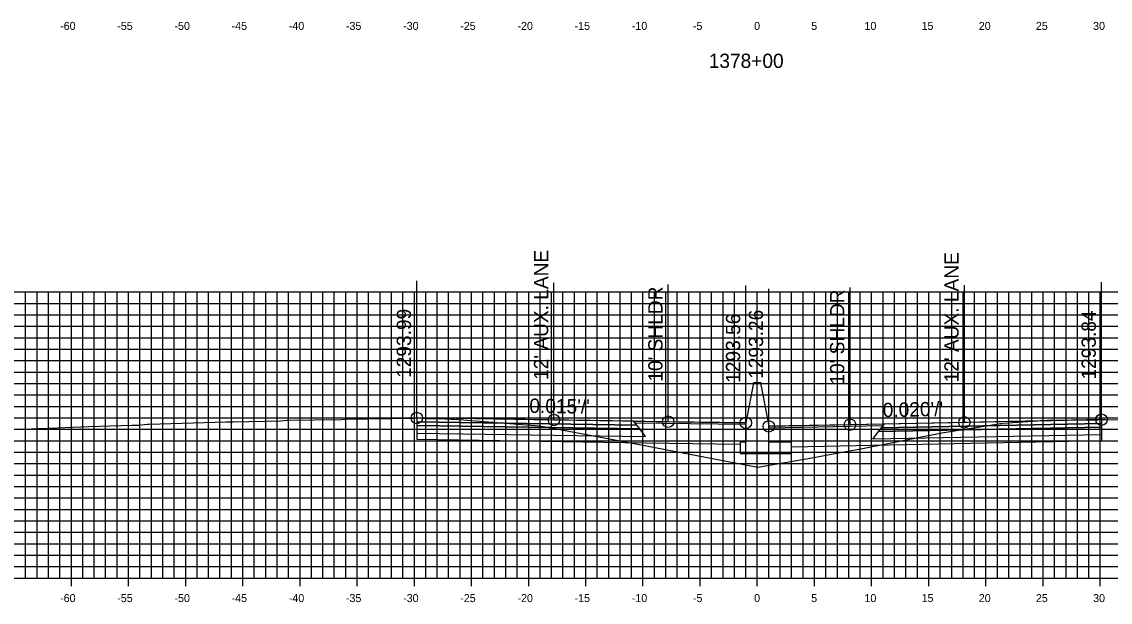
# Model space of a CAD drawing. Extents: x 674939 to 678919, y 750652 to 765176.
# Drawn here: x 678674.2 to 678769.4, y 754945.4 to 754996.2 of the extents above; entities that cross this region are included whole.
import ezdxf

# ---------------------------------------------------------------- set-up
doc = ezdxf.new("R2010")
doc.units = 0
for name, color, linetype in [('Level 10', 7, 'Continuous'), ('Level 17', 7, 'Continuous'), ('Level 18', 7, 'Continuous'), ('Level 19', 7, 'Continuous'), ('Level 20', 7, 'Continuous'), ('Level 22', 7, 'Continuous'), ('Level 23', 7, 'Continuous'), ('Level 4', 7, 'Continuous'), ('Level 8', 7, 'Continuous'), ('Level 9', 7, 'Continuous')]:
    doc.layers.add(name, color=color, linetype=linetype)

msp = doc.modelspace()

# ---------------------------------------------------------------- linework, layer by layer
at = {"layer": 'Level 10'}
msp.add_lwpolyline([(678674.013, 754960.526), (678675.52, 754960.608), (678675.907, 754960.628), (678680.049, 754960.81), (678683.814, 754960.912), (678683.991, 754960.917), (678684.367, 754960.917), (678684.438, 754960.92), (678685.15, 754960.998), (678685.171, 754960.999), (678685.211, 754961.004), (678685.297, 754961.007), (678692.07, 754961.198), (678692.403, 754961.208), (678692.676, 754961.214), (678696.815, 754961.296), (678697.379, 754961.349), (678697.439, 754961.352), (678702.14, 754961.42), (678702.534, 754961.427), (678708.484, 754961.534), (678708.743, 754961.539), (678708.81, 754961.541), (678708.815, 754961.541), (678709.567, 754961.486), (678709.663, 754961.481), (678710.415, 754961.467), (678710.603, 754961.491), (678710.663, 754961.491), (678711.791, 754961.422), (678711.979, 754961.435), (678712.051, 754961.431), (678712.615, 754961.392), (678712.625, 754961.393), (678712.819, 754961.388), (678713.156, 754961.36), (678719.456, 754960.855), (678721.566, 754960.47), (678728.221, 754959.227), (678730.645, 754958.765), (678738.575, 754957.235), (678743.461, 754958.101), (678745.322, 754958.426), (678747.586, 754958.839), (678754.67, 754960.231), (678757.057, 754960.62), (678760.02, 754961.084), (678762.197, 754961.232), (678764.288, 754961.367), (678764.355, 754961.352), (678764.444, 754961.335), (678764.863, 754961.325), (678765.702, 754961.354), (678766.424, 754961.374), (678766.844, 754961.374), (678767.823, 754961.371), (678768.123, 754961.366), (678768.318, 754961.375), (678768.641, 754961.395), (678768.747, 754961.4), (678768.983, 754961.414), (678772.412, 754961.361)], dxfattribs=at)
at = {"layer": 'Level 17'}
for points in [[(678738.203, 754964.615), (678737.533, 754961.115)], [(678738.863, 754964.313), (678738.863, 754964.615), (678738.203, 754964.615), (678738.203, 754964.615)], [(678738.863, 754964.313), (678739.533, 754960.813)], [(678737.533, 754961.115), (678737.533, 754959.438), (678737.033, 754959.438), (678737.033, 754958.438), (678741.533, 754958.438), (678741.533, 754959.438), (678739.533, 754959.438), (678739.533, 754960.813)]]:
    msp.add_lwpolyline(points, dxfattribs=at)
at = {"layer": 'Level 18'}
for points in [[(678737.533, 754961.115), (678730.743, 754961.215), (678720.743, 754961.362), (678708.743, 754961.539)], [(678768.641, 754961.395), (678756.641, 754961.155), (678746.641, 754960.955), (678739.533, 754960.813)]]:
    msp.add_lwpolyline(points, dxfattribs=at)
for points in [[(678708.743, 754961.539), (678708.743, 754961.209), (678727.993, 754960.924), (678727.743, 754961.259)], [(678727.743, 754961.259), (678737.533, 754961.115), (678737.537, 754960.957), (678727.862, 754961.099)], [(678749.522, 754960.855), (678739.533, 754960.655), (678739.533, 754960.813), (678749.641, 754961.015)], [(678768.641, 754961.395), (678768.641, 754961.065), (678749.391, 754960.68), (678749.641, 754961.015)]]:
    msp.add_lwpolyline(points, close=True, dxfattribs=at)
at = {"layer": 'Level 19'}
for points in [[(678708.743, 754961.209), (678708.743, 754960.879), (678728.243, 754960.589), (678727.993, 754960.924)], [(678708.743, 754960.879), (678708.743, 754960.219), (678728.743, 754959.919), (678728.243, 754960.589)], [(678768.641, 754960.735), (678768.641, 754960.075), (678748.641, 754959.675), (678749.141, 754960.345)], [(678768.641, 754961.065), (678768.641, 754960.735), (678749.141, 754960.345), (678749.391, 754960.68)]]:
    msp.add_lwpolyline(points, close=True, dxfattribs=at)
for points in [[(678708.743, 754960.219), (678708.743, 754959.679), (678728.743, 754959.379), (678737.033, 754959.255)], [(678768.641, 754960.075), (678768.641, 754959.535), (678748.641, 754959.135), (678741.533, 754958.993)]]:
    msp.add_lwpolyline(points, dxfattribs=at)
at = {"layer": 'Level 20'}
for p, q in [((678638.533, 754972.551), (678838.533, 754972.551)), ((678674.533, 754947.551), (678674.533, 754972.551)), ((678675.533, 754947.551), (678675.533, 754972.551)), ((678676.533, 754947.551), (678676.533, 754972.551)), ((678677.533, 754947.551), (678677.533, 754972.551)), ((678678.533, 754947.551), (678678.533, 754972.551)), ((678679.533, 754947.551), (678679.533, 754972.551)), ((678680.533, 754947.551), (678680.533, 754972.551)), ((678681.533, 754947.551), (678681.533, 754972.551)), ((678682.533, 754947.551), (678682.533, 754972.551)), ((678683.533, 754947.551), (678683.533, 754972.551)), ((678684.533, 754947.551), (678684.533, 754972.551)), ((678685.533, 754947.551), (678685.533, 754972.551)), ((678686.533, 754947.551), (678686.533, 754972.551)), ((678687.533, 754947.551), (678687.533, 754972.551)), ((678688.533, 754947.551), (678688.533, 754972.551)), ((678689.533, 754947.551), (678689.533, 754972.551)), ((678690.533, 754947.551), (678690.533, 754972.551)), ((678691.533, 754947.551), (678691.533, 754972.551)), ((678692.533, 754947.551), (678692.533, 754972.551)), ((678693.533, 754947.551), (678693.533, 754972.551)), ((678694.533, 754947.551), (678694.533, 754972.551)), ((678695.533, 754947.551), (678695.533, 754972.551)), ((678696.533, 754947.551), (678696.533, 754972.551)), ((678697.533, 754947.551), (678697.533, 754972.551)), ((678698.533, 754947.551), (678698.533, 754972.551)), ((678699.533, 754947.551), (678699.533, 754972.551)), ((678700.533, 754947.551), (678700.533, 754972.551)), ((678701.533, 754947.551), (678701.533, 754972.551)), ((678702.533, 754947.551), (678702.533, 754972.551)), ((678703.533, 754947.551), (678703.533, 754972.551)), ((678704.533, 754947.551), (678704.533, 754972.551)), ((678705.533, 754947.551), (678705.533, 754972.551)), ((678706.533, 754947.551), (678706.533, 754972.551)), ((678707.533, 754947.551), (678707.533, 754972.551)), ((678708.533, 754947.551), (678708.533, 754972.551)), ((678709.533, 754947.551), (678709.533, 754972.551)), ((678710.533, 754947.551), (678710.533, 754972.551)), ((678711.533, 754947.551), (678711.533, 754972.551)), ((678712.533, 754947.551), (678712.533, 754972.551)), ((678713.533, 754947.551), (678713.533, 754972.551)), ((678714.533, 754947.551), (678714.533, 754972.551)), ((678715.533, 754947.551), (678715.533, 754972.551)), ((678716.533, 754947.551), (678716.533, 754972.551)), ((678717.533, 754947.551), (678717.533, 754972.551)), ((678718.533, 754947.551), (678718.533, 754972.551)), ((678719.533, 754947.551), (678719.533, 754972.551)), ((678720.533, 754947.551), (678720.533, 754972.551)), ((678721.533, 754947.551), (678721.533, 754972.551)), ((678722.533, 754947.551), (678722.533, 754972.551)), ((678723.533, 754947.551), (678723.533, 754972.551)), ((678724.533, 754947.551), (678724.533, 754972.551)), ((678725.533, 754947.551), (678725.533, 754972.551)), ((678726.533, 754947.551), (678726.533, 754972.551)), ((678727.533, 754947.551), (678727.533, 754972.551)), ((678728.533, 754947.551), (678728.533, 754972.551)), ((678729.533, 754947.551), (678729.533, 754972.551)), ((678730.533, 754947.551), (678730.533, 754972.551)), ((678731.533, 754947.551), (678731.533, 754972.551)), ((678732.533, 754947.551), (678732.533, 754972.551)), ((678733.533, 754947.551), (678733.533, 754972.551)), ((678734.533, 754947.551), (678734.533, 754972.551)), ((678735.533, 754947.551), (678735.533, 754972.551)), ((678736.533, 754947.551), (678736.533, 754972.551)), ((678737.533, 754947.551), (678737.533, 754972.551)), ((678738.533, 754947.551), (678738.533, 754972.551)), ((678739.533, 754947.551), (678739.533, 754972.551)), ((678740.533, 754947.551), (678740.533, 754972.551)), ((678741.533, 754947.551), (678741.533, 754972.551)), ((678742.533, 754947.551), (678742.533, 754972.551)), ((678743.533, 754947.551), (678743.533, 754972.551)), ((678744.533, 754947.551), (678744.533, 754972.551)), ((678745.533, 754947.551), (678745.533, 754972.551)), ((678746.533, 754947.551), (678746.533, 754972.551)), ((678747.533, 754947.551), (678747.533, 754972.551)), ((678748.533, 754947.551), (678748.533, 754972.551)), ((678749.533, 754947.551), (678749.533, 754972.551)), ((678750.533, 754947.551), (678750.533, 754972.551)), ((678751.533, 754947.551), (678751.533, 754972.551)), ((678752.533, 754947.551), (678752.533, 754972.551)), ((678753.533, 754947.551), (678753.533, 754972.551)), ((678754.533, 754947.551), (678754.533, 754972.551)), ((678755.533, 754947.551), (678755.533, 754972.551)), ((678756.533, 754947.551), (678756.533, 754972.551)), ((678757.533, 754947.551), (678757.533, 754972.551)), ((678758.533, 754947.551), (678758.533, 754972.551)), ((678759.533, 754947.551), (678759.533, 754972.551)), ((678760.533, 754947.551), (678760.533, 754972.551)), ((678761.533, 754947.551), (678761.533, 754972.551)), ((678762.533, 754947.551), (678762.533, 754972.551)), ((678763.533, 754947.551), (678763.533, 754972.551)), ((678764.533, 754947.551), (678764.533, 754972.551)), ((678765.533, 754947.551), (678765.533, 754972.551)), ((678766.533, 754947.551), (678766.533, 754972.551)), ((678767.533, 754947.551), (678767.533, 754972.551)), ((678768.533, 754947.551), (678768.533, 754972.551)), ((678638.533, 754971.551), (678838.533, 754971.551)), ((678638.533, 754970.551), (678838.533, 754970.551)), ((678638.533, 754969.551), (678838.533, 754969.551)), ((678638.533, 754968.551), (678838.533, 754968.551)), ((678638.533, 754967.551), (678838.533, 754967.551)), ((678638.533, 754966.551), (678838.533, 754966.551)), ((678638.533, 754965.551), (678838.533, 754965.551)), ((678638.533, 754964.551), (678838.533, 754964.551)), ((678638.533, 754963.551), (678838.533, 754963.551)), ((678638.533, 754962.551), (678838.533, 754962.551)), ((678638.533, 754961.551), (678838.533, 754961.551)), ((678638.533, 754960.551), (678838.533, 754960.551)), ((678638.533, 754959.551), (678838.533, 754959.551)), ((678638.533, 754958.551), (678838.533, 754958.551)), ((678638.533, 754957.551), (678838.533, 754957.551)), ((678638.533, 754956.551), (678838.533, 754956.551)), ((678638.533, 754955.551), (678838.533, 754955.551)), ((678638.533, 754954.551), (678838.533, 754954.551)), ((678638.533, 754953.551), (678838.533, 754953.551)), ((678638.533, 754952.551), (678838.533, 754952.551)), ((678638.533, 754951.551), (678838.533, 754951.551)), ((678638.533, 754950.551), (678838.533, 754950.551)), ((678638.533, 754949.551), (678838.533, 754949.551)), ((678638.533, 754948.551), (678838.533, 754948.551)), ((678638.533, 754947.551), (678838.533, 754947.551))]:
    msp.add_line(p, q, dxfattribs=at)
at = {"layer": 'Level 23'}
for p, q in [((678708.743, 754961.539), (678708.743, 754973.539)), ((678720.743, 754961.362), (678720.743, 754973.362)), ((678730.743, 754961.215), (678730.743, 754973.215)), ((678737.533, 754961.115), (678737.533, 754973.115)), ((678746.641, 754960.955), (678746.641, 754972.955)), ((678756.641, 754961.155), (678756.641, 754973.155)), ((678768.641, 754961.395), (678768.641, 754973.395)), ((678739.533, 754960.813), (678739.533, 754972.813))]:
    msp.add_line(p, q, dxfattribs=at)
at = {"layer": 'Level 4'}
for centre in [(678708.743, 754961.539), (678720.743, 754961.362), (678730.743, 754961.215), (678737.533, 754961.115), (678746.641, 754960.955), (678756.641, 754961.155), (678768.641, 754961.395), (678739.533, 754960.813)]:
    msp.add_circle(centre, 0.5, dxfattribs=at)
at = {"layer": 'Level 8'}
for p, q in [((678678.533, 754946.851), (678678.533, 754948.251)), ((678683.533, 754946.851), (678683.533, 754948.251)), ((678688.533, 754946.851), (678688.533, 754948.251)), ((678693.533, 754946.851), (678693.533, 754948.251)), ((678698.533, 754946.851), (678698.533, 754948.251)), ((678703.533, 754946.851), (678703.533, 754948.251)), ((678708.533, 754946.851), (678708.533, 754948.251)), ((678713.533, 754946.851), (678713.533, 754948.251)), ((678718.533, 754946.851), (678718.533, 754948.251)), ((678723.533, 754946.851), (678723.533, 754948.251)), ((678728.533, 754946.851), (678728.533, 754948.251)), ((678733.533, 754946.851), (678733.533, 754948.251)), ((678738.533, 754946.851), (678738.533, 754948.251)), ((678743.533, 754946.851), (678743.533, 754948.251)), ((678748.533, 754946.851), (678748.533, 754948.251)), ((678753.533, 754946.851), (678753.533, 754948.251)), ((678758.533, 754946.851), (678758.533, 754948.251)), ((678763.533, 754946.851), (678763.533, 754948.251)), ((678768.533, 754946.851), (678768.533, 754948.251)), ((678638.533, 754947.551), (678838.533, 754947.551))]:
    msp.add_line(p, q, dxfattribs=at)

# ---------------------------------------------------------------- texts
at = {"layer": 'Level 22'}
for s, rotation, p in [("0.015'/'", 359.1572, (678718.584, 754961.994)), ("0.020'/'", 1.14576, (678749.513, 754961.612))]:
    msp.add_text(s, height=1.25, rotation=rotation, dxfattribs=at).set_placement(p)
at = {"layer": 'Level 23'}
for s, p in [("12' AUX. LANE", (678720.243, 754964.862)), ("12' AUX. LANE", (678756.141, 754964.655)), ("10' SHLDR", (678730.243, 754964.715)), ("10' SHLDR", (678746.141, 754964.455)), ('1293.99', (678708.243, 754965.039)), ('1293.56', (678737.033, 754964.615)), ('1293.26', (678739.033, 754964.954)), ('1293.84', (678768.141, 754964.895))]:
    msp.add_text(s, height=1.25, rotation=90, dxfattribs=at).set_placement(p)
at = {"layer": 'Level 9'}
for s, height, p in [('-60', 0.7, (678677.552, 754995.451)), ('-55', 0.7, (678682.546, 754995.451)), ('-50', 0.7, (678687.552, 754995.451)), ('-45', 0.7, (678692.546, 754995.451)), ('-40', 0.7, (678697.552, 754995.451)), ('-35', 0.7, (678702.546, 754995.451)), ('-30', 0.7, (678707.552, 754995.451)), ('-25', 0.7, (678712.546, 754995.451)), ('-20', 0.7, (678717.552, 754995.451)), ('-15', 0.7, (678722.546, 754995.451)), ('-10', 0.7, (678727.552, 754995.451)), ('-5', 0.7, (678732.896, 754995.451)), ('0', 0.7, (678738.252, 754995.451)), ('5', 0.7, (678743.246, 754995.451)), ('10', 0.7, (678747.902, 754995.451)), ('15', 0.7, (678752.896, 754995.451)), ('20', 0.7, (678757.902, 754995.451)), ('25', 0.7, (678762.896, 754995.451)), ('30', 0.7, (678767.902, 754995.451)), ('1378+00', 1.25, (678734.281, 754992.126)), ('-60', 0.7, (678677.552, 754945.451)), ('-55', 0.7, (678682.546, 754945.451)), ('-50', 0.7, (678687.552, 754945.451)), ('-45', 0.7, (678692.546, 754945.451)), ('-40', 0.7, (678697.552, 754945.451)), ('-35', 0.7, (678702.546, 754945.451)), ('-30', 0.7, (678707.552, 754945.451)), ('-25', 0.7, (678712.546, 754945.451)), ('-20', 0.7, (678717.552, 754945.451)), ('-15', 0.7, (678722.546, 754945.451)), ('-10', 0.7, (678727.552, 754945.451)), ('-5', 0.7, (678732.896, 754945.451)), ('0', 0.7, (678738.252, 754945.451)), ('5', 0.7, (678743.246, 754945.451)), ('10', 0.7, (678747.902, 754945.451)), ('15', 0.7, (678752.896, 754945.451)), ('20', 0.7, (678757.902, 754945.451)), ('25', 0.7, (678762.896, 754945.451)), ('30', 0.7, (678767.902, 754945.451))]:
    msp.add_text(s, height=height, dxfattribs=at).set_placement(p)

doc.saveas('drawing.dxf')
